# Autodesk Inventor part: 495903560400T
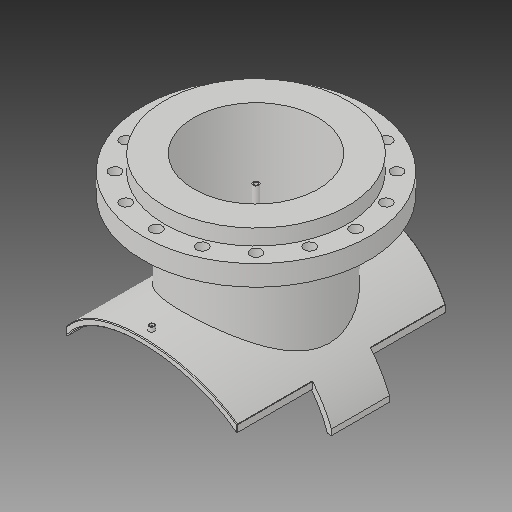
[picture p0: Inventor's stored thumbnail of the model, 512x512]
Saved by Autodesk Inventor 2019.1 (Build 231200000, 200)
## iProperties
Created: 2017-10
Part Number: 495903560400T
Material: Generic
Description: PLASSON FLANGED BRANCH SADDLE 560X400
Document SubType Name: Modeling
Designer: KIM
Mass: 2339.99 g
Surface Area: 3251.55 cm^2
Volume: 2339.99 cm^3
Density: 1 g/cm^3
Appearance: Default
Author: KIM
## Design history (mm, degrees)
derived "495904_495903.ipt"
feature "Solid1::495904_495903.ipt"
feature "Solid2::495904_495903.ipt"
tag "TaggingFeature1"
body "Solid1"
other parameters: "d1" = 15, "d4" = 0, "d6" = 152.5, "d7" = 0, "d12" = 305.6, "d13" = 14, "d14" = 274.5, "d16" = 5 deg, "d18" = 4, "d19" = 14, "d20" = 0, "d21" = 3, "d22" = 0, "d23" = 575, "d36" = 274.5, "d38" = 0, "d39" = 2, "d41" = 327, "d42" = 482, "d43" = 595, "d44" = 224, "d46" = 385.6, "d47" = 16, "d48" = 10.4, "d49" = 196, "d51" = 571.2, "d53" = 0, "d55" = 262.5, "d57" = 0, "d59" = 360 deg, "d61" = 54, "d63" = 0, "d67" = 15, "d70" = 0, "d71" = 2, "d_1" = 482, "x_" = 15, "D_" = 16, "DN_" = 327, "D_1" = 595, "t_" = 54, "Dp_" = 525
